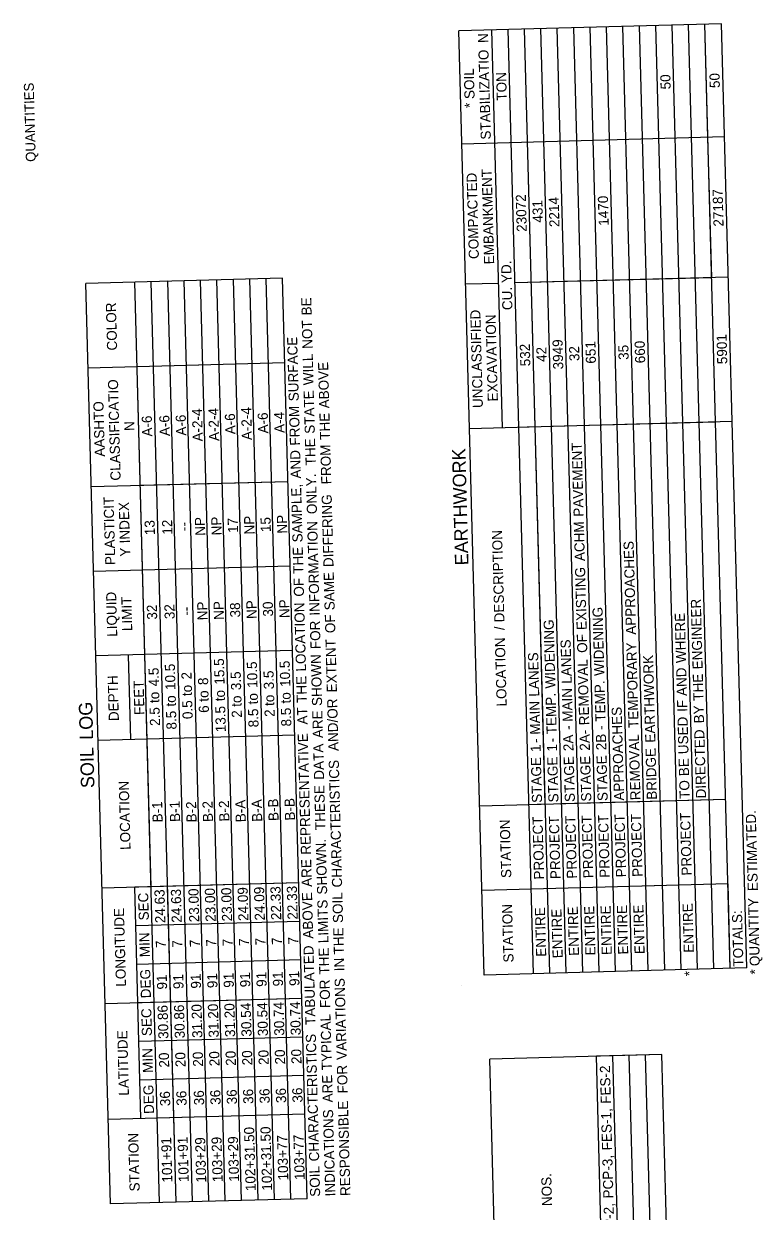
# Model space of a CAD drawing. Extents: x 1930091 to 1931962, y 596452 to 607874.
# Drawn here: x 1930226 to 1930662, y 602254 to 602960 of the extents above; entities that cross this region are included whole.
import ezdxf

# ---------------------------------------------------------------- set-up
doc = ezdxf.new("R2010")
doc.units = 0
for name, color, linetype in [('Default', 7, 'Continuous'), ('R_Border', 7, 'Continuous'), ('S_AREA_CALC', 7, 'Continuous')]:
    doc.layers.add(name, color=color, linetype=linetype)

msp = doc.modelspace()

# ---------------------------------------------------------------- linework, layer by layer
at = {"layer": 'Default'}
for p, q in [((1930640.51, 602959.79), (1930484.57, 602955.61)), ((1930640.51, 602959.79), (1930484.57, 602955.61)), ((1930558.1, 602396.26), (1930543.04, 602957.18)), ((1930567.85, 602396.53), (1930552.79, 602957.44)), ((1930577.59, 602396.79), (1930562.54, 602957.7)), ((1930587.34, 602397.05), (1930572.28, 602957.96)), ((1930597.09, 602397.31), (1930582.03, 602958.22)), ((1930606.83, 602397.57), (1930591.78, 602958.48)), ((1930616.58, 602397.83), (1930601.52, 602958.74)), ((1930626.33, 602398.1), (1930611.27, 602959.01)), ((1930636.07, 602398.36), (1930621.02, 602959.27)), ((1930645.82, 602398.62), (1930630.76, 602959.53)), ((1930632.57, 602892.28), (1930630.76, 602959.53)), ((1930655.57, 602398.88), (1930640.51, 602959.79)), ((1930499.62, 602394.69), (1930484.57, 602955.61)), ((1930510.4, 602719.78), (1930504.06, 602956.13)), ((1930528.86, 602395.48), (1930513.81, 602956.39)), ((1930538.61, 602395.74), (1930523.55, 602956.65)), ((1930529.9, 602720.3), (1930523.55, 602956.65)), ((1930548.36, 602396), (1930533.3, 602956.91)), ((1930642.31, 602892.54), (1930486.37, 602888.35)), ((1930634.81, 602808.95), (1930632.57, 602892.28)), ((1930644.55, 602809.21), (1930517.85, 602805.81)), ((1930634.81, 602808.95), (1930517.85, 602805.81)), ((1930379.75, 602808.62), (1930262.8, 602805.48)), ((1930277.47, 602258.71), (1930262.8, 602805.48)), ((1930306.71, 602259.49), (1930292.04, 602806.27)), ((1930297.98, 602585.02), (1930292.04, 602806.27)), ((1930311.53, 602806.79), (1930301.78, 602806.53)), ((1930316.46, 602259.75), (1930301.78, 602806.53)), ((1930326.21, 602260.01), (1930311.53, 602806.79)), ((1930335.95, 602260.28), (1930321.28, 602807.05)), ((1930345.7, 602260.54), (1930331.02, 602807.31)), ((1930355.45, 602260.8), (1930340.77, 602807.58)), ((1930365.19, 602261.06), (1930350.52, 602807.84)), ((1930374.94, 602261.32), (1930360.26, 602808.1)), ((1930384.69, 602261.58), (1930370.01, 602808.36)), ((1930394.43, 602261.84), (1930379.75, 602808.62)), ((1930394.43, 602261.84), (1930379.75, 602808.62)), ((1930508.1, 602805.55), (1930488.61, 602805.02)), ((1930381.1, 602758.43), (1930264.14, 602755.29)), ((1930381.1, 602758.43), (1930293.38, 602756.07)), ((1930646.85, 602723.44), (1930490.91, 602719.25)), ((1930529.9, 602720.3), (1930520.15, 602720.04)), ((1930535.91, 602496.13), (1930529.9, 602720.3)), ((1930637.11, 602723.18), (1930539.64, 602720.56)), ((1930383, 602687.77), (1930266.04, 602684.63)), ((1930383, 602687.77), (1930295.28, 602685.41)), ((1930384.35, 602637.57), (1930267.39, 602634.43)), ((1930384.35, 602637.57), (1930296.63, 602635.22)), ((1930385.69, 602587.38), (1930268.74, 602584.24)), ((1930289.58, 602534.57), (1930288.23, 602584.76)), ((1930301.68, 602447.11), (1930297.98, 602585.02)), ((1930387.04, 602537.18), (1930270.08, 602534.04)), ((1930387.04, 602537.18), (1930299.32, 602534.83)), ((1930643.13, 602499.01), (1930496.93, 602495.08)), ((1930643.13, 602499.01), (1930545.66, 602496.39)), ((1930535.91, 602496.13), (1930526.17, 602495.87)), ((1930389.4, 602449.46), (1930272.44, 602446.33)), ((1930389.4, 602449.46), (1930291.93, 602446.85)), ((1930295.62, 602309.42), (1930291.93, 602446.85)), ((1930316.46, 602259.75), (1930311.42, 602447.37)), ((1930644.47, 602448.81), (1930498.28, 602444.89)), ((1930644.47, 602448.81), (1930527.51, 602445.67)), ((1930645.82, 602398.62), (1930644.47, 602448.81)), ((1930390.01, 602426.56), (1930292.55, 602423.94)), ((1930390.01, 602426.56), (1930292.55, 602423.94)), ((1930390.63, 602403.66), (1930293.16, 602401.04)), ((1930390.63, 602403.66), (1930293.16, 602401.04)), ((1930655.57, 602398.88), (1930499.62, 602394.69)), ((1930655.57, 602398.88), (1930499.62, 602394.69)), ((1930391.24, 602380.75), (1930274.28, 602377.61)), ((1930391.24, 602380.75), (1930293.78, 602378.14)), ((1930391.86, 602357.85), (1930294.39, 602355.23)), ((1930391.86, 602357.85), (1930294.39, 602355.23)), ((1930605.24, 602347.54), (1930502.9, 602344.79)), ((1930527.01, 601446.65), (1930502.9, 602344.79)), ((1930605.24, 602347.54), (1930566.25, 602346.49)), ((1930590.36, 601448.35), (1930566.25, 602346.49)), ((1930571.67, 602144.74), (1930566.25, 602346.49)), ((1930600.11, 601448.61), (1930576, 602346.75)), ((1930609.85, 601448.88), (1930585.74, 602347.01)), ((1930619.6, 601449.14), (1930595.49, 602347.28)), ((1930602.24, 602095.82), (1930595.49, 602347.28)), ((1930629.35, 601449.4), (1930605.24, 602347.54)), ((1930392.47, 602334.94), (1930295.01, 602332.33)), ((1930392.47, 602334.94), (1930295.01, 602332.33)), ((1930393.08, 602312.04), (1930276.13, 602308.9)), ((1930393.08, 602312.04), (1930305.37, 602309.68)), ((1930394.43, 602261.84), (1930277.47, 602258.71)), ((1930394.43, 602261.84), (1930277.47, 602258.71))]:
    msp.add_line(p, q, dxfattribs=at)
at = {"layer": 'R_Border'}
msp.add_line((1930486.13, 602388.48), (1930486.13, 602388.48), dxfattribs=at)

# ---------------------------------------------------------------- texts
at = {"layer": 'Default'}
for s, height, p in [('N', 6, (1930502.01, 602948.45)), ('STABILIZATIO', 6, (1930503.55, 602891.05)), (' SOIL', 6, (1930493.96, 602912.93)), ('TON', 6, (1930513.06, 602914.2)), ('50', 6, (1930610.42, 602920.87)), ('50', 6, (1930639.66, 602921.66)), ('*', 6, (1930494.05, 602909.84)), ('EMBANKMENT', 6, (1930505.54, 602816.97)), ('COMPACTED', 6, (1930496.46, 602820.11)), ('27187', 6, (1930641.87, 602839.36)), ('23072', 6, (1930524.91, 602836.26)), ('431', 6, (1930534.51, 602841.73)), ('2214', 6, (1930544.34, 602839.09)), ('1470', 6, (1930573.58, 602839.88)), (' YD.', 6, (1930516.03, 602803.61)), ('CU.', 6, (1930516.4, 602789.75)), (' BE', 6, (1930397.14, 602784.37)), ('COLOR', 6, (1930281.49, 602765.75)), ('UNCLASSIFIED', 6, (1930498.83, 602731.6)), (' NOT', 6, (1930397.67, 602764.52)), ('EXCAVATION', 6, (1930507.73, 602735.46)), ('5901', 6, (1930644.06, 602757.64)), (' SURFACE', 6, (1930389.5, 602733.4)), ('532', 6, (1930527.05, 602756.37)), ('42', 6, (1930536.74, 602758.96)), ('3949', 6, (1930546.61, 602754.53)), ('32', 6, (1930556.23, 602759.48)), ('651', 6, (1930566.02, 602757.96)), ('35', 6, (1930585.47, 602760.21)), ('660', 6, (1930595.28, 602758.18)), (' WILL', 6, (1930398.25, 602742.94)), (' ABOVE', 6, (1930407.62, 602729.16)), ('CLASSIFICATIO', 6, (1930283.57, 602688.47)), (' STATE', 6, (1930399.02, 602714.05)), ('AASHTO', 6, (1930274.18, 602702.66)), ('A-2-4', 6, (1930342.13, 602711.98)), ('A-2-4', 6, (1930361.63, 602712.5)), (' FROM', 6, (1930390.21, 602707.04)), ('A-6', 6, (1930302.37, 602714.62)), ('A-6', 6, (1930312.8, 602714.9)), ('A-6', 6, (1930322.54, 602715.17)), ('A-2-4', 6, (1930332.39, 602711.72)), ('A-6', 6, (1930351.78, 602715.95)), ('A-6', 6, (1930371.27, 602716.47)), ('A-4', 6, (1930381.02, 602716.75)), (' THE', 6, (1930408.12, 602710.52)), ('N', 6, (1930291.78, 602717.98)), ('  THE', 6, (1930399.59, 602693.08)), (' PAVEMENT', 6, (1930558.77, 602664.8)), (' AND', 6, (1930390.73, 602687.46)), ('  FROM', 6, (1930408.89, 602681.82)), ('EARTHWORK', 8, (1930490.26, 602638.15)), (' ONLY.', 6, (1930400.31, 602666.34)), (' SAMPLE,', 6, (1930391.75, 602649.55)), ('PLASTICIT', 6, (1930280.41, 602638.32)), (' INDEX', 6, (1930289.13, 602648.96)), (' DIFFERING', 6, (1930410.15, 602634.86)), ('13', 6, (1930303.95, 602656.06)), ('12', 6, (1930314.37, 602656.37)), ('--', 6, (1930324.07, 602658.41)), ('NP', 6, (1930333.89, 602655.69)), ('NP', 6, (1930343.64, 602655.95)), ('17', 6, (1930353.35, 602657.38)), ('NP', 6, (1930363.13, 602656.47)), ('15', 6, (1930372.85, 602657.88)), ('NP', 6, (1930382.62, 602657)), (' INFORMATION', 6, (1930401.92, 602606.03)), (' ACHM', 6, (1930559.48, 602638.42)), (' DESCRIPTION', 6, (1930511.69, 602602.05)), ('Y', 6, (1930289.28, 602643.36)), (' THE', 6, (1930392.25, 602630.91)), (' APPROACHES', 6, (1930589.91, 602594.66)), (' SAME', 6, (1930410.84, 602609.23)), (' EXISTING', 6, (1930560.58, 602597.5)), (' OF', 6, (1930392.62, 602617.32)), ('LIQUID', 6, (1930281.56, 602595.7)), ('LIMIT', 6, (1930290.47, 602599.08)), ('32', 6, (1930305.29, 602605.89)), ('32', 6, (1930315.71, 602606.17)), ('--', 6, (1930325.41, 602608.21)), ('NP', 6, (1930335.24, 602605.5)), ('NP', 6, (1930344.99, 602605.76)), ('38', 6, (1930354.7, 602607.18)), ('NP', 6, (1930364.48, 602606.28)), ('30', 6, (1930374.19, 602607.72)), ('NP', 6, (1930383.97, 602606.8)), (' LOCATION', 6, (1930393.81, 602572.84)), (' WIDENING', 6, (1930571.06, 602570.25)), (' ENGINEER', 6, (1930629.48, 602574.15)), (' FOR', 6, (1930402.46, 602586.13)), (' OF', 6, (1930411.21, 602595.64)), (' WIDENING', 6, (1930542, 602562.78)), (' WHERE', 6, (1930619.63, 602577.87)), (' /', 6, (1930511.81, 602597.39)), (' EXTENT', 6, (1930412.15, 602560.42)), ('LOCATION', 6, (1930512.97, 602554.3)), (' LANES', 6, (1930551.68, 602565.58)), (' OF', 6, (1930560.94, 602583.92)), (' TEMPORARY', 6, (1930591.4, 602539.31)), (' SHOWN', 6, (1930403.36, 602552.36)), (' LANES', 6, (1930532.38, 602557.91)), (' EARTHWORK', 6, (1930601.39, 602530.57)), (' 4.5', 6, (1930306.42, 602564)), (' 10.5', 6, (1930316.23, 602561.87)), (' 15.5', 6, (1930345.4, 602565.05)), (' 10.5', 6, (1930364.96, 602563.18)), (' 10.5', 6, (1930384.45, 602563.7)), (' REMOVAL', 6, (1930562.1, 602540.91)), (' AND', 6, (1930620.15, 602558.29)), ('DEPTH', 6, (1930282.53, 602545.6)), ('FEET', 6, (1930297.73, 602549.27)), (' 2', 6, (1930325.81, 602568.1)), (' 8', 6, (1930335.66, 602564.8)), (' 3.5', 6, (1930355.25, 602561.74)), (' 3.5', 6, (1930374.74, 602562.26)), (' THE', 6, (1930394.31, 602554.2)), (' THE', 6, (1930629.98, 602555.51)), (' to', 6, (1930306.68, 602554.14)), (' to', 6, (1930326.08, 602558.23)), (' to', 6, (1930335.92, 602554.93)), (' to', 6, (1930345.67, 602555.18)), (' to', 6, (1930384.72, 602553.84)), (' MAIN', 6, (1930552.29, 602542.99)), (' TEMP.', 6, (1930571.79, 602543.05)), (' LOG', 8, (1930267.32, 602531.57)), (' to', 6, (1930316.49, 602552)), ('0.5', 6, (1930326.39, 602546.82)), (' to', 6, (1930355.51, 602551.87)), (' to', 6, (1930365.23, 602553.31)), (' to', 6, (1930375, 602552.39)), (' AND/OR', 6, (1930413.09, 602525.61)), (' MAIN', 6, (1930532.99, 602535.32)), (' TEMP.', 6, (1930542.73, 602535.58)), (' IF', 6, (1930620.4, 602548.9)), ('2.5', 6, (1930306.99, 602542.73)), ('8.5', 6, (1930316.8, 602540.59)), ('6', 6, (1930336.04, 602550.51)), ('13.5', 6, (1930346.1, 602538.99)), ('2', 6, (1930355.63, 602547.61)), ('8.5', 6, (1930365.53, 602541.9)), ('2', 6, (1930375.12, 602548.13)), ('8.5', 6, (1930385.02, 602542.43)), (' AT', 6, (1930394.66, 602541.33)), (' ARE', 6, (1930403.88, 602533.25)), ('APPROACHES', 6, (1930582.75, 602498.36)), (' BY', 6, (1930630.34, 602542.06)), (' -', 6, (1930552.42, 602538.13)), (' -', 6, (1930571.92, 602538.19)), (' USED', 6, (1930621.08, 602523.73)), (' REPRESENTATIVE', 6, (1930396.73, 602464)), (' -', 6, (1930533.12, 602530.46)), (' -', 6, (1930542.86, 602530.72)), (' 2A', 6, (1930552.76, 602525.54)), (' 2A-', 6, (1930562.5, 602525.8)), (' 2B', 6, (1930572.25, 602526.07)), ('REMOVAL', 6, (1930592.49, 602498.62)), ('DIRECTED', 6, (1930631.48, 602499.67)), ('SOIL', 8, (1930268.01, 602505.83)), (' DATA', 6, (1930404.54, 602508.55)), (' 1', 6, (1930533.26, 602525.02)), (' 1', 6, (1930543.01, 602525.28)), ('BRIDGE', 6, (1930602.24, 602498.89)), (' CHARACTERISTICS', 6, (1930415.26, 602444.56)), ('STAGE', 6, (1930534.01, 602497.05)), ('STAGE', 6, (1930543.76, 602497.32)), ('STAGE', 6, (1930553.51, 602497.58)), ('STAGE', 6, (1930563.25, 602497.84)), ('STAGE', 6, (1930573, 602498.1)), (' BE', 6, (1930621.43, 602510.67)), ('LOCATION', 6, (1930289.46, 602469.11)), ('  THESE', 6, (1930405.4, 602476.4)), ('TO', 6, (1930621.73, 602499.41)), ('B-A', 6, (1930357.97, 602485.51)), ('B-A', 6, (1930367.71, 602485.78)), ('B-B', 6, (1930377.45, 602486.27)), ('B-B', 6, (1930387.2, 602486.53)), ('B-1', 6, (1930308.53, 602485.43)), ('B-1', 6, (1930318.95, 602485.71)), ('B-2', 6, (1930328.71, 602485.42)), ('B-2', 6, (1930338.46, 602485.69)), ('B-2', 6, (1930348.2, 602485.95)), (' ESTIMATED.', 6, (1930662.28, 602442.38)), ('STATION', 6, (1930515.71, 602452.4)), ('PROJECT', 6, (1930535.24, 602451.51)), ('PROJECT', 6, (1930544.98, 602451.77)), ('PROJECT', 6, (1930554.73, 602452.03)), ('PROJECT', 6, (1930564.48, 602452.29)), ('PROJECT', 6, (1930574.22, 602452.55)), ('PROJECT', 6, (1930583.97, 602452.82)), ('PROJECT', 6, (1930593.72, 602453.08)), ('PROJECT', 6, (1930622.95, 602453.86)), (' SHOWN.', 6, (1930406.37, 602440.36)), (' ARE', 6, (1930397.25, 602444.89)), ('SEC', 6, (1930300.34, 602427.21)), ('24.63', 6, (1930310.13, 602425.58)), ('24.63', 6, (1930319.88, 602425.84)), ('23.00', 6, (1930330.3, 602426.13)), ('23.00', 6, (1930340.05, 602426.39)), ('23.00', 6, (1930349.79, 602426.65)), ('24.09', 6, (1930359.54, 602426.9)), ('24.09', 6, (1930369.29, 602427.16)), ('22.33', 6, (1930379.03, 602427.43)), ('22.33', 6, (1930388.78, 602427.69)), (' ABOVE', 6, (1930398.07, 602414.12)), (' SOIL', 6, (1930415.83, 602423.44)), (' LIMITS', 6, (1930407.15, 602411.46)), ('STATION', 6, (1930517.05, 602402.21)), ('ENTIRE', 6, (1930555.96, 602406.17)), ('ENTIRE', 6, (1930565.71, 602406.43)), ('ENTIRE', 6, (1930575.45, 602406.69)), ('ENTIRE', 6, (1930585.2, 602406.95)), ('ENTIRE', 6, (1930594.95, 602407.21)), ('ENTIRE', 6, (1930624.19, 602408)), ('QUANTITY', 6, (1930663.41, 602400.07)), ('LONGITUDE', 6, (1930286.76, 602387.84)), ('ENTIRE', 6, (1930536.47, 602405.65)), ('ENTIRE', 6, (1930546.25, 602404.74)), ('TOTALS:', 6, (1930653.67, 602399.81)), (' THE', 6, (1930416.33, 602404.79)), ('MIN', 6, (1930300.92, 602405.36)), ('7', 6, (1930310.53, 602410.83)), ('7', 6, (1930320.28, 602411.09)), ('7', 6, (1930330.7, 602411.37)), ('7', 6, (1930340.44, 602411.63)), ('7', 6, (1930350.19, 602411.89)), ('7', 6, (1930359.94, 602412.15)), ('7', 6, (1930369.68, 602412.41)), ('7', 6, (1930379.43, 602412.68)), ('7', 6, (1930389.18, 602412.94)), (' TABULATED', 6, (1930399.45, 602362.88)), (' THE', 6, (1930407.65, 602392.82)), (' IN', 6, (1930416.6, 602394.77)), ('DEG', 6, (1930301.58, 602380.97)), ('91', 6, (1930311.19, 602386.17)), ('91', 6, (1930320.94, 602386.43)), ('91', 6, (1930331.36, 602386.71)), ('91', 6, (1930341.11, 602386.98)), ('91', 6, (1930350.85, 602387.24)), ('91', 6, (1930360.6, 602387.5)), ('91', 6, (1930370.34, 602387.76)), ('91', 6, (1930380.09, 602388.02)), ('91', 6, (1930389.84, 602388.28)), ('*', 6, (1930624.56, 602394.1)), ('*', 6, (1930663.54, 602395.15)), (' FOR', 6, (1930408.18, 602372.92)), (' VARIATIONS', 6, (1930418.01, 602342.12)), ('30.74', 6, (1930390.62, 602358.99)), ('SEC', 6, (1930302.18, 602358.49)), ('30.86', 6, (1930311.98, 602356.87)), ('30.86', 6, (1930321.72, 602357.13)), ('31.20', 6, (1930332.15, 602357.42)), ('31.20', 6, (1930341.89, 602357.68)), ('31.20', 6, (1930351.64, 602357.94)), ('30.54', 6, (1930361.38, 602358.21)), ('30.54', 6, (1930371.13, 602358.47)), ('30.74', 6, (1930380.88, 602358.73)), (' TYPICAL', 6, (1930409.17, 602335.96)), ('LATITUDE', 6, (1930288.5, 602323.09)), (' CHARACTERISTICS', 6, (1930401.62, 602281.82)), ('MIN', 6, (1930302.77, 602336.65)), ('20', 6, (1930391.08, 602341.91)), ('20', 6, (1930312.44, 602339.8)), ('20', 6, (1930322.18, 602340.06)), ('20', 6, (1930332.6, 602340.34)), ('20', 6, (1930342.35, 602340.6)), ('20', 6, (1930352.1, 602340.86)), ('20', 6, (1930361.84, 602341.12)), ('20', 6, (1930371.59, 602341.38)), ('20', 6, (1930381.34, 602341.64)), (' FOR', 6, (1930418.55, 602322.22)), (' FES-2', 6, (1930574.95, 602316.06)), (' ARE', 6, (1930409.69, 602316.84)), ('DEG', 6, (1930303.42, 602312.26)), ('36', 6, (1930313.05, 602316.88)), ('36', 6, (1930322.8, 602317.14)), ('36', 6, (1930333.22, 602317.42)), ('36', 6, (1930342.97, 602317.68)), ('36', 6, (1930352.71, 602317.94)), ('36', 6, (1930362.46, 602318.21)), ('36', 6, (1930372.2, 602318.47)), ('36', 6, (1930381.95, 602318.73)), ('36', 6, (1930391.7, 602318.99)), ('RESPONSIBLE', 6, (1930420.12, 602263.51)), ('INDICATIONS', 6, (1930411.13, 602263.27)), (' FES-1,', 6, (1930575.69, 602288.4)), ('102+31.50', 6, (1930363.85, 602266.41)), ('102+31.50', 6, (1930373.6, 602266.67)), ('STATION', 6, (1930294.9, 602266.22)), ('101+91', 6, (1930314.27, 602271.48)), ('101+91', 6, (1930324.02, 602271.74)), ('103+29', 6, (1930334.45, 602271.43)), ('103+29', 6, (1930344.2, 602271.7)), ('103+29', 6, (1930353.95, 602271.96)), ('103+77', 6, (1930383.19, 602272.75)), ('103+77', 6, (1930392.93, 602273.01)), (' PCP-3,', 6, (1930576.46, 602259.81)), ('SOIL', 6, (1930402.13, 602263.03)), (' NOS.', 6, (1930540, 602255.26)), (' PCP-2,', 6, (1930577.22, 602231.22))]:
    msp.add_text(s, height=height, rotation=91.53769, dxfattribs=at).set_placement(p)
at = {"layer": 'S_AREA_CALC'}
msp.add_text('QUANTITIES', height=5.862, rotation=91.53769, dxfattribs=at).set_placement((1930233.13, 602877.83))

doc.saveas('drawing.dxf')
